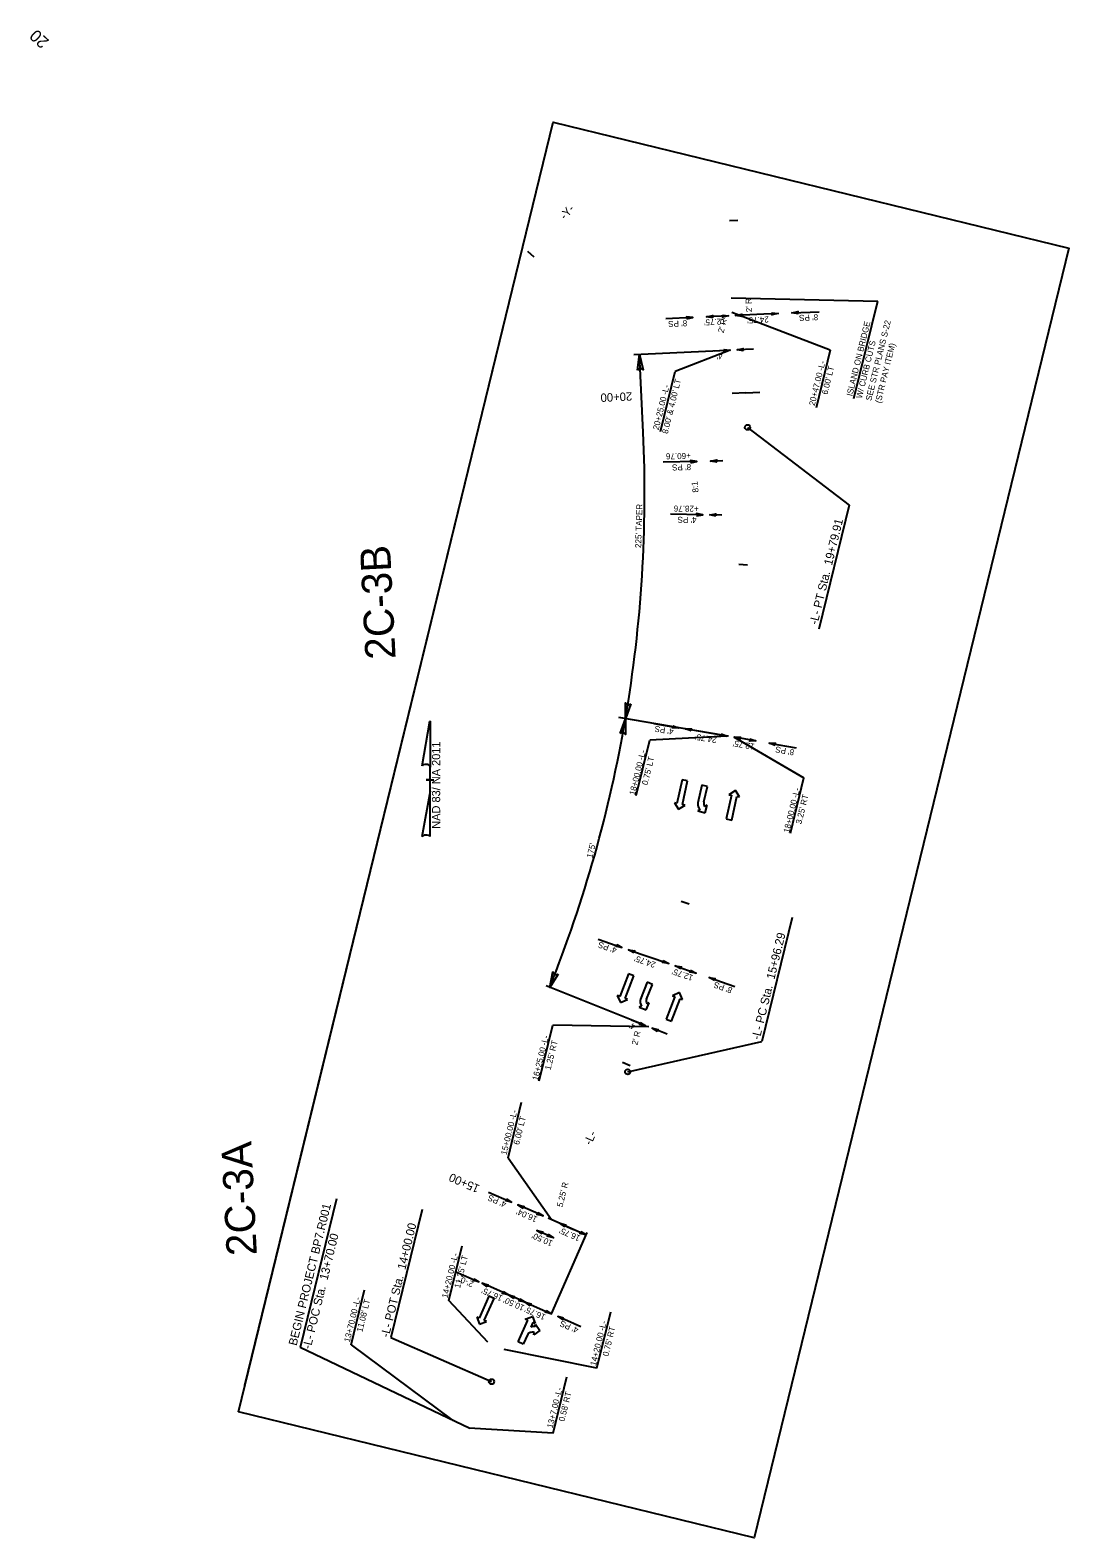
# Model space of a CAD drawing. Extents: x 1807485 to 1808169, y 913841 to 915733.
# Drawn here: x 1807485 to 1808087, y 913841 to 914715 of the extents above; entities that cross this region are included whole.
import ezdxf

# ---------------------------------------------------------------- set-up
doc = ezdxf.new("R2010")
doc.units = 0
for name, color, linetype in [('Prop Dimension', 7, 'Continuous'), ('Prop Horizontal Alignment Direction Label', 7, 'Continuous'), ('Prop Horizontal Alignment Station Label', 7, 'Continuous'), ('Prop Horizontal Alignment Tick Label', 7, 'Continuous'), ('Prop Horizontal Alignment Tick Large', 7, 'Continuous'), ('Prop Horizontal Alignment Tick Small', 7, 'Continuous'), ('Prop Lane Arrow CELL', 7, 'Continuous'), ('Prop North Arrow NAD83 for Plan Sheets CELL', 7, 'Continuous'), ('Prop Terminator CELL', 7, 'Continuous'), ('Scratch_Level_3', 7, 'Continuous'), ('Scratch_Level_6', 7, 'Continuous')]:
    doc.layers.add(name, color=color, linetype=linetype)

msp = doc.modelspace()

# ---------------------------------------------------------------- linework, layer by layer
at = {"layer": 'Prop Dimension'}
for p, q in [((1807891.51, 914560.27), (1807976.52, 914558.31)), ((1807962.73, 914501.81), (1807976.52, 914558.31)), ((1807891.9, 914551.85), (1807949.01, 914529.99)), ((1807889.09, 914529.7), (1807835.05, 914527.19)), ((1807840.43, 914482.3), (1807838.34, 914527.35)), ((1807890.92, 914529.78), (1807858.99, 914517.49)), ((1807940.95, 914496.62), (1807949.14, 914530.16)), ((1807850.49, 914482.65), (1807858.99, 914517.49)), ((1807887.49, 914306.31), (1807826.25, 914316.8)), ((1807836.35, 914271.49), (1807844.2, 914303.63)), ((1807889.19, 914306.02), (1807844.2, 914303.63)), ((1807893.14, 914305.34), (1807933.67, 914281.78)), ((1807925.83, 914249.64), (1807933.67, 914281.78)), ((1807840.16, 914138.72), (1807784.14, 914161.08)), ((1807780.08, 914106.14), (1807787.93, 914138.28)), ((1807843.71, 914137.3), (1807787.93, 914138.28)), ((1807845.57, 914136.56), (1807845.57, 914136.56)), ((1807762.02, 914061.5), (1807769.87, 914093.65)), ((1807727.65, 913978.6), (1807735.41, 914010.4)), ((1807670.91, 913953.01), (1807678.68, 913984.81)), ((1807750.2, 913954.43), (1807727.65, 913978.6)), ((1807813.6, 913939.39), (1807821.58, 913972.06)), ((1807670.91, 913953.01), (1807729.95, 913909.1)), ((1807813.6, 913939.39), (1807759.81, 913950.21)), ((1807788.16, 913901.72), (1807796.13, 913934.39)), ((1807788.16, 913901.72), (1807739.41, 913904.58))]:
    msp.add_line(p, q, dxfattribs=at)
msp.add_lwpolyline([(1807762.02, 914061.5), (1807787.2, 914025.56)], dxfattribs=at)
for start, end in [(350.27869, 2.65322), (338.24176, 350.27869)]:
    msp.add_arc((1807068.89, 914446.55), 772.36, start, end, dxfattribs=at)
at = {"layer": 'Prop Horizontal Alignment Station Label'}
for p, q in [((1807901, 914485.11), (1807959.86, 914439.92)), ((1807959.86, 914439.92), (1807942.29, 914367.96)), ((1807926.88, 914200.88), (1807909.31, 914128.92)), ((1807831.45, 914111.28), (1807909.31, 914128.92)), ((1807662.55, 914037.72), (1807641.47, 913951.36)), ((1807712.14, 914031.44), (1807694.04, 913957.28)), ((1807694.04, 913957.28), (1807752.44, 913931.6)), ((1807739.94, 913904.33), (1807641.47, 913951.36))]:
    msp.add_line(p, q, dxfattribs=at)
for centre in [(1807901, 914485.11), (1807831.45, 914111.28), (1807752.44, 913931.6)]:
    msp.add_circle(centre, 1.5, dxfattribs=at)
at = {"layer": 'Prop Horizontal Alignment Tick Large'}
for p, q in [((1807900.07, 914505.18), (1807892.08, 914504.81)), ((1807900.07, 914505.18), (1807908.06, 914505.55)), ((1807792.69, 914023.14), (1807785.37, 914026.36)), ((1807792.69, 914023.14), (1807800.02, 914019.92))]:
    msp.add_line(p, q, dxfattribs=at)
at = {"layer": 'Prop Horizontal Alignment Tick Small'}
for p, q in [((1807895.44, 914605.07), (1807890.45, 914604.84)), ((1807777.23, 914583.78), (1807773.53, 914587.15)), ((1807900.87, 914405.23), (1807895.87, 914405.48)), ((1807889.93, 914305.89), (1807885, 914306.74)), ((1807867.18, 914208.58), (1807862.39, 914210.01)), ((1807832.93, 914114.69), (1807828.35, 914116.68))]:
    msp.add_line(p, q, dxfattribs=at)
at = {"layer": 'Prop Lane Arrow CELL'}
for p, q in [((1807863.01, 914280.7), (1807860.04, 914267.02)), ((1807866.24, 914279.99), (1807863.01, 914280.7)), ((1807863.26, 914266.31), (1807866.24, 914279.99)), ((1807874.5, 914277.5), (1807872.13, 914267.22)), ((1807877.72, 914276.76), (1807874.5, 914277.5)), ((1807875.66, 914267.84), (1807877.72, 914276.76)), ((1807891.63, 914271.72), (1807888.65, 914258.04)), ((1807893.96, 914274.44), (1807890.16, 914272.04)), ((1807890.16, 914272.04), (1807891.63, 914271.72)), ((1807891.87, 914257.34), (1807894.85, 914271.02)), ((1807896.32, 914270.7), (1807893.96, 914274.44)), ((1807894.85, 914271.02), (1807896.32, 914270.7)), ((1807860.04, 914267.02), (1807858.57, 914267.33)), ((1807858.57, 914267.33), (1807860.93, 914263.6)), ((1807860.93, 914263.6), (1807864.73, 914265.99)), ((1807864.73, 914265.99), (1807863.26, 914266.31)), ((1807873.41, 914263.39), (1807872.15, 914262.6)), ((1807872.15, 914262.6), (1807876.43, 914261.56)), ((1807877.48, 914265.94), (1807876.23, 914265.15)), ((1807876.43, 914261.56), (1807877.48, 914265.94)), ((1807888.65, 914258.04), (1807891.87, 914257.34)), ((1807831.84, 914168.12), (1807826.82, 914155.05)), ((1807829.9, 914153.86), (1807834.92, 914166.93)), ((1807834.92, 914166.93), (1807831.84, 914168.12)), ((1807826.82, 914155.05), (1807825.42, 914155.59)), ((1807825.42, 914155.59), (1807827.19, 914151.53)), ((1807842.71, 914163.22), (1807838.81, 914153.41)), ((1807842.4, 914153.5), (1807845.78, 914162)), ((1807845.78, 914162), (1807842.71, 914163.22)), ((1807858.76, 914154.91), (1807853.74, 914141.84)), ((1807861.48, 914157.24), (1807857.36, 914155.44)), ((1807857.36, 914155.44), (1807858.76, 914154.91)), ((1807863.24, 914153.18), (1807861.48, 914157.24)), ((1807827.19, 914151.53), (1807831.3, 914153.33)), ((1807831.3, 914153.33), (1807829.9, 914153.86)), ((1807839.49, 914149.43), (1807838.13, 914148.84)), ((1807838.13, 914148.84), (1807842.2, 914147.17)), ((1807842.2, 914147.17), (1807843.91, 914151.33)), ((1807843.91, 914151.33), (1807842.54, 914150.75)), ((1807856.82, 914140.65), (1807861.84, 914153.72)), ((1807861.84, 914153.72), (1807863.24, 914153.18)), ((1807853.74, 914141.84), (1807856.82, 914140.65)), ((1807750.91, 913981.25), (1807745.2, 913968.46)), ((1807748.21, 913967.12), (1807753.92, 913979.9)), ((1807753.92, 913979.9), (1807750.91, 913981.25)), ((1807745.2, 913968.46), (1807743.83, 913969.07)), ((1807743.83, 913969.07), (1807745.37, 913964.93)), ((1807745.37, 913964.93), (1807749.58, 913966.51)), ((1807749.58, 913966.51), (1807748.21, 913967.12)), ((1807767.81, 913954.61), (1807773.42, 913967.21)), ((1807772.05, 913967.82), (1807776.19, 913969.37)), ((1807773.42, 913967.21), (1807772.05, 913967.82)), ((1807776.43, 913965.87), (1807775.27, 913963.27)), ((1807776.19, 913969.37), (1807777.8, 913965.26)), ((1807777.8, 913965.26), (1807776.43, 913965.87)), ((1807777.64, 913963.42), (1807777.86, 913964.91)), ((1807777.86, 913964.91), (1807780.49, 913961.33)), ((1807770.82, 913953.26), (1807767.81, 913954.61)), ((1807773.44, 913959.16), (1807770.82, 913953.26)), ((1807780.49, 913961.33), (1807776.91, 913958.71)), ((1807776.91, 913958.71), (1807777.12, 913960.15))]:
    msp.add_line(p, q, dxfattribs=at)
for centre, radius, start, end in [((1807877.36, 914266.83), 5.25, 175.72703, 221.03872), ((1807878.84, 914267.1), 3.27, 167.05095, 216.70913), ((1807843.91, 914152.24), 5.25, 166.99581, 212.3075), ((1807845.42, 914152.28), 3.27, 158.31973, 207.97791), ((1807776.69, 913959.08), 4.43, 77.59062, 108.46921), ((1807775.42, 913957.58), 2.52, 105.0729, 141.3849), ((1807776.17, 913955.81), 4.43, 77.70943, 108.56298)]:
    msp.add_arc(centre, radius, start, end, dxfattribs=at)
at = {"layer": 'Prop North Arrow NAD83 for Plan Sheets CELL'}
for p, q in [((1807712.13, 914288.77), (1807716.72, 914314.73)), ((1807716.75, 914314.73), (1807716.72, 914314.73)), ((1807716.75, 914314.73), (1807716.72, 914314.73)), ((1807716.75, 914314.73), (1807716.75, 914287.96)), ((1807716.75, 914274.07), (1807716.75, 914288.75)), ((1807716.75, 914287.96), (1807716.75, 914288.72)), ((1807714.51, 914280.57), (1807714.48, 914280.57)), ((1807716.5, 914280.57), (1807714.51, 914280.57)), ((1807714.54, 914280.57), (1807719.02, 914280.57)), ((1807716.75, 914274.07), (1807712.07, 914247.61)), ((1807716.78, 914247.73), (1807716.75, 914274.07))]:
    msp.add_line(p, q, dxfattribs=at)
for centre, start_param, end_param in [((1807714.45, 914288.5), 0.216388, 2.908219), ((1807714.45, 914247.52), 0.201328, 3.141593)]:
    msp.add_ellipse(centre, major_axis=(2.37, -0.02), ratio=0.461098, start_param=start_param, end_param=end_param, dxfattribs=at)
at = {"layer": 'Prop Terminator CELL'}
for points in [[(1807837.21, 914518.28), (1807838.34, 914527.35), (1807840.36, 914518.38), (1807838.71, 914519.45)], [(1807833.21, 914324.74), (1807830.16, 914316.13), (1807830.12, 914325.32), (1807831.5, 914323.92)], [(1807827.12, 914307.52), (1807830.16, 914316.13), (1807830.21, 914306.94), (1807828.83, 914308.34)], [(1807791.01, 914168.03), (1807786.23, 914160.24), (1807788.1, 914169.24), (1807789.16, 914167.58)]]:
    msp.add_lwpolyline(points, close=True, dxfattribs=at)
at = {"layer": 'Scratch_Level_3'}
msp.add_line((1807609.35, 913929.53), (1807759.2, 914543.26), dxfattribs=at)
msp.add_lwpolyline([(1807605.57, 913914.04), (1807788.21, 914662.07), (1808087.42, 914589.02), (1807904.78, 913840.99)], close=True, dxfattribs=at)
at = {"layer": 'Scratch_Level_6'}
for p, q in [((1807869.27, 914548.8), (1807853.49, 914548.07)), ((1807890, 914549.76), (1807877.26, 914549.17)), ((1807918.72, 914551.09), (1807893.99, 914549.95)), ((1807926.71, 914551.46), (1807942.49, 914552.19)), ((1807890.92, 914529.78), (1807881.69, 914529.35)), ((1807904.35, 914530.41), (1807894.92, 914529.97)), ((1807871.58, 914465.27), (1807852.06, 914464.82)), ((1807886.59, 914465.62), (1807879.57, 914465.46)), ((1807875.02, 914434.38), (1807856.29, 914434.66)), ((1807886.04, 914434.21), (1807879.02, 914434.32)), ((1807846.55, 914313.32), (1807860.86, 914310.87)), ((1807889.19, 914306.02), (1807864.8, 914310.2)), ((1807905.7, 914303.19), (1807893.14, 914305.34)), ((1807913.59, 914301.84), (1807929.13, 914299.18)), ((1807814.38, 914188.21), (1807828.1, 914183.45)), ((1807831.88, 914182.14), (1807855.26, 914174.04)), ((1807859.04, 914172.73), (1807871.09, 914168.56)), ((1807878.65, 914165.94), (1807893.63, 914160.75)), ((1807841.85, 914138.04), (1807833.59, 914141.34)), ((1807854.34, 914133.06), (1807845.57, 914136.56)), ((1807750.63, 914041.58), (1807764.04, 914035.69)), ((1807782.39, 914027.67), (1807767.71, 914034.12)), ((1807788.33, 914015.09), (1807778.72, 914019.31)), ((1807787.22, 913970.93), (1807807.95, 914018.09)), ((1807792.01, 914023.44), (1807807.34, 914016.7)), ((1807731.8, 913995.25), (1807745.09, 913989.4)), ((1807762.27, 913981.9), (1807746.94, 913988.64)), ((1807771.88, 913977.67), (1807762.27, 913981.9)), ((1807771.88, 913977.67), (1807787.22, 913970.93)), ((1807804.28, 913963.43), (1807790.88, 913969.32))]:
    msp.add_line(p, q, dxfattribs=at)
for points in [[(1807865.7, 914548.01), (1807869.27, 914548.8), (1807865.62, 914549.27), (1807866.11, 914548.65)], [(1807880.88, 914548.72), (1807877.26, 914549.17), (1807880.85, 914549.98), (1807880.42, 914549.32)], [(1807886.37, 914550.21), (1807890, 914549.76), (1807886.41, 914548.95), (1807886.84, 914549.61)], [(1807897.62, 914549.49), (1807893.99, 914549.95), (1807897.58, 914550.75), (1807897.15, 914550.09)], [(1807915.09, 914551.54), (1807918.72, 914551.09), (1807915.13, 914550.29), (1807915.56, 914550.95)], [(1807930.33, 914551.01), (1807926.71, 914551.46), (1807930.29, 914552.27), (1807929.86, 914551.61)], [(1807887.3, 914530.24), (1807890.92, 914529.78), (1807887.34, 914528.98), (1807887.77, 914529.64)], [(1807898.54, 914529.52), (1807894.92, 914529.97), (1807898.5, 914530.77), (1807898.07, 914530.11)], [(1807868, 914464.57), (1807871.58, 914465.27), (1807867.95, 914465.83), (1807868.43, 914465.2)], [(1807883.18, 914464.92), (1807879.57, 914465.46), (1807883.17, 914466.18), (1807882.73, 914465.53)], [(1807871.41, 914433.81), (1807875.02, 914434.38), (1807871.41, 914435.07), (1807871.86, 914434.43)], [(1807882.61, 914433.65), (1807879.02, 914434.32), (1807882.65, 914434.9), (1807882.18, 914434.27)], [(1807857.63, 914312.02), (1807860.86, 914310.87), (1807857.41, 914310.86), (1807857.94, 914311.37)], [(1807868.24, 914308.98), (1807864.8, 914310.2), (1807868.47, 914310.22), (1807867.91, 914309.66)], [(1807885.75, 914307.24), (1807889.19, 914306.02), (1807885.52, 914306), (1807886.08, 914306.55)], [(1807896.58, 914304.12), (1807893.14, 914305.34), (1807896.81, 914305.36), (1807896.25, 914304.81)], [(1807902.26, 914304.41), (1807905.7, 914303.19), (1807902.03, 914303.17), (1807902.59, 914303.72)], [(1807917.03, 914300.62), (1807913.59, 914301.84), (1807917.26, 914301.86), (1807916.7, 914301.31)], [(1807825.1, 914185.11), (1807828.1, 914183.45), (1807824.7, 914184), (1807825.3, 914184.42)], [(1807835.08, 914180.38), (1807831.88, 914182.14), (1807835.51, 914181.56), (1807834.86, 914181.11)], [(1807852.07, 914175.8), (1807855.26, 914174.04), (1807851.63, 914174.62), (1807852.28, 914175.07)], [(1807862.24, 914170.97), (1807859.04, 914172.73), (1807862.67, 914172.15), (1807862.03, 914171.7)], [(1807867.89, 914170.32), (1807871.09, 914168.56), (1807867.46, 914169.14), (1807868.11, 914169.59)], [(1807881.85, 914164.17), (1807878.65, 914165.94), (1807882.28, 914165.36), (1807881.64, 914164.9)], [(1807838.74, 914139.95), (1807841.85, 914138.04), (1807838.25, 914138.79), (1807838.92, 914139.21)], [(1807848.68, 914134.65), (1807845.57, 914136.56), (1807849.17, 914135.81), (1807848.5, 914135.39)], [(1807761.18, 914037.58), (1807764.04, 914035.69), (1807760.69, 914036.51), (1807761.32, 914036.88)], [(1807770.76, 914032.11), (1807767.71, 914034.12), (1807771.29, 914033.25), (1807770.61, 914032.85)], [(1807779.35, 914029.69), (1807782.39, 914027.67), (1807778.82, 914028.54), (1807779.5, 914028.94)], [(1807781.77, 914017.3), (1807778.72, 914019.31), (1807782.29, 914018.44), (1807781.61, 914018.04)], [(1807785.29, 914017.11), (1807788.33, 914015.09), (1807784.76, 914015.96), (1807785.44, 914016.36)], [(1807795.05, 914021.43), (1807792.01, 914023.44), (1807795.58, 914022.57), (1807794.9, 914022.17)], [(1807804.29, 914018.72), (1807807.34, 914016.7), (1807803.77, 914017.57), (1807804.45, 914017.97)], [(1807742.23, 913991.29), (1807745.09, 913989.4), (1807741.74, 913990.22), (1807742.38, 913990.6)], [(1807749.98, 913986.62), (1807746.94, 913988.64), (1807750.51, 913987.77), (1807749.83, 913987.37)], [(1807759.22, 913983.91), (1807762.27, 913981.9), (1807758.7, 913982.77), (1807759.38, 913983.17)], [(1807765.32, 913979.88), (1807762.27, 913981.9), (1807765.84, 913981.03), (1807765.16, 913980.63)], [(1807768.84, 913979.69), (1807771.88, 913977.67), (1807768.31, 913978.54), (1807768.99, 913978.94)], [(1807774.93, 913975.65), (1807771.88, 913977.67), (1807775.45, 913976.8), (1807774.78, 913976.4)], [(1807784.17, 913972.95), (1807787.22, 913970.93), (1807783.64, 913971.8), (1807784.32, 913972.2)], [(1807794.2, 913968.49), (1807790.88, 913969.32), (1807793.74, 913967.4), (1807793.59, 913968.13)]]:
    msp.add_lwpolyline(points, close=True, dxfattribs=at)

# ---------------------------------------------------------------- texts
at = {"layer": 'Prop Dimension'}
for s, rotation, p in [("2' R", 76.27912, (1807887.08, 914539.61)), ('ISLAND ON BRIDGE', 76.27912, (1807961.75, 914502.95)), ('SEE STR PLANS S-22', 76.27912, (1807972.8, 914500.25)), ('W/ CURB CUTS', 76.27912, (1807967.28, 914501.6)), ('(STR PAY ITEM)', 76.27912, (1807978.33, 914498.9)), ('20+47.00 -L-', 76.27912, (1807939.91, 914497.36)), ("8.00' & 4.00' LT", 76.27912, (1807854.69, 914481.1)), ("6.00' LT", 76.27912, (1807947.35, 914503.86)), ('20+25.00 -L-', 76.27912, (1807849.38, 914483.35)), ("225' TAPER", 88.16224, (1807839.22, 914415.05)), ('18+00.00 -L-', 76.27912, (1807835.67, 914271.49)), ("0.75' LT", 76.27912, (1807842.96, 914277.35)), ('18+00.00 -L-', 76.27912, (1807925.15, 914249.64)), ("3.25' RT", 76.27912, (1807932.24, 914254.7)), ("175'", 76.27912, (1807810.9, 914235.01)), ('16+25.00 -L-', 76.27912, (1807779.38, 914106.03)), ("1.25' RT", 76.27912, (1807786.71, 914112.08)), ("2' R", 76.27912, (1807837.06, 914126.57)), ('15+00.00 -L-', 76.27912, (1807761.13, 914062.81)), ("6.00' LT", 76.27912, (1807768.43, 914068.7)), ("5.25' R", 76.27912, (1807793.63, 914032.56)), ('14+20.00 -L-', 76.27912, (1807726.89, 913979.8)), ("11.25' LT", 76.27912, (1807734.15, 913985.55)), ('13+70.00 -L-', 76.27912, (1807670.17, 913954.25)), ("11.08' LT", 76.27912, (1807677.45, 913960.11)), ('14+20.00 -L-', 76.27912, (1807812.98, 913940.55)), ("0.75' RT", 76.27912, (1807820.17, 913946.04)), ('13+7.00 -L-', 76.27912, (1807787.89, 913904.36)), ("0.58' RT", 76.27912, (1807794.69, 913908.23))]:
    msp.add_text(s, height=3.5, rotation=rotation, dxfattribs=at).set_placement(p)
at = {"layer": 'Prop Horizontal Alignment Direction Label'}
for s, rotation, p in [('-Y-', 47.65322, (1807795.07, 914605.14)), ('-L-', 66.2667, (1807810.21, 914068.4))]:
    msp.add_text(s, height=4.9, rotation=rotation, dxfattribs=at).set_placement(p)
at = {"layer": 'Prop Horizontal Alignment Station Label'}
for s, p in [('-L- PT Sta.  19+79.91', (1807941.57, 914370.41)), ('-L- PC Sta.  15+96.29', (1807908.02, 914129.56)), ('BEGIN PROJECT BP7.R001', (1807639.33, 913952.18)), ('-L- POC Sta.  13+70.00', (1807647.49, 913950.19)), ('-L- POT Sta.  14+00.00', (1807692.82, 913956.94))]:
    msp.add_text(s, height=4.9, rotation=76.27912, dxfattribs=at).set_placement(p)
at = {"layer": 'Prop Horizontal Alignment Tick Label'}
for s, height, rotation, p in [('20', 7, 137.65322, (1807496.13, 914709.41)), ('20+00', 4.9, 182.65322, (1807833.95, 914505.54)), ('15+00', 4.9, 156.2667, (1807745.98, 914045.29))]:
    msp.add_text(s, height=height, rotation=rotation, dxfattribs=at).set_placement(p)
at = {"layer": 'Prop North Arrow NAD83 for Plan Sheets CELL'}
msp.add_text('NAD 83/ NA 2011', height=4.76, rotation=90, dxfattribs=at).set_placement((1807722.64, 914252.29))
at = {"layer": 'Scratch_Level_3'}
for s, p in [('2C-3B', (1807696.82, 914350.89)), ('2C-3A', (1807616.32, 914005.01))]:
    msp.add_text(s, height=17.5, rotation=92.84221, dxfattribs=at).set_placement(p)
at = {"layer": 'Scratch_Level_6'}
for s, rotation, p in [("2' R", 92.84221, (1807903.64, 914551.93)), ("24.75'", 182.65322, (1807913.21, 914549.46)), ("8' PS", 182.65322, (1807941.85, 914550.78)), ("8' PS", 182.65322, (1807865.89, 914547.26)), ("12.75'", 182.65322, (1807888.22, 914548.3)), ("4'", 182.65322, (1807886.42, 914528.2)), ('+60.76', 181.33634, (1807868.02, 914470.33)), ("8' PS", 181.33634, (1807868.18, 914463.82)), ('8:1', 96.34541, (1807872.61, 914447.49)), ('+28.76', 179.13511, (1807872.64, 914439.55)), ("4' PS", 179.13511, (1807871.45, 914433.06)), ("4' PS", 170.27869, (1807858.3, 914310.21)), ("24.75'", 170.27869, (1807883.32, 914305.26)), ("12.75'", 170.27869, (1807905.22, 914301.51)), ("8' PS", 170.27869, (1807928.34, 914298.21)), ("4' PS", 160.88672, (1807825.47, 914183.22)), ("24.75'", 160.88672, (1807847.96, 914174.78)), ("12.75'", 160.88672, (1807869.76, 914167.22)), ("8' PS", 160.88672, (1807892.53, 914159.98)), ("4'", 158.24176, (1807836.35, 914138.76)), ("4' PS", 156.2667, (1807761.39, 914035.67)), ("16.04'", 156.2667, (1807779.32, 914027.01)), ("10.50'", 156.2667, (1807788.3, 914013.1)), ("16.75'", 156.2667, (1807804.27, 914016.04)), ('2\'-0"', 156.2667, (1807742.45, 913989.38)), ("16.75'", 156.2667, (1807759.2, 913981.24)), ("10.50'", 156.2667, (1807771.85, 913975.68)), ("16.75'", 156.2667, (1807784.14, 913970.27)), ("4' PS", 156.2667, (1807803.21, 913962.71))]:
    msp.add_text(s, height=3.5, rotation=rotation, dxfattribs=at).set_placement(p)

doc.saveas('drawing.dxf')
